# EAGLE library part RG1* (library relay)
HIGH FREQUENCY RELAYS WITH 1C AND 2C CONTACTS NAiS Source: http://www.mew-europe.com/.. en_ds_61302_0000.pdf
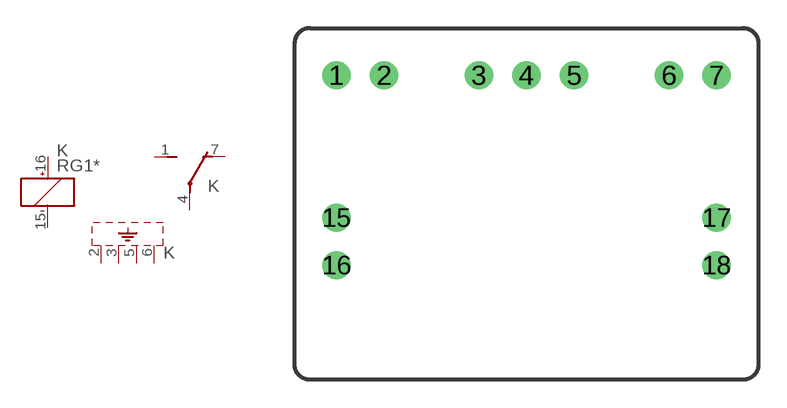
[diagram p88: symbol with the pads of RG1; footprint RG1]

Designator prefix K; gates G$1=K+- G$2=U G$3=SHIELD-4

## RG1-3V (OC_FARNELL: unknown; OC_NEWARK: unknown), RG1-5V (OC_FARNELL: unknown; OC_NEWARK: unknown), RG1-6V (OC_FARNELL: unknown; OC_NEWARK: unknown), RG1-9V (OC_FARNELL: unknown; OC_NEWARK: unknown), RG1-12V (OC_FARNELL: unknown; OC_NEWARK: unknown), RG1-24V (OC_FARNELL: unknown; OC_NEWARK: unknown), RG1-48V (OC_FARNELL: unknown; OC_NEWARK: unknown), RG1T-3V (OC_FARNELL: unknown; OC_NEWARK: unknown), RG1T-5V (OC_FARNELL: unknown; OC_NEWARK: unknown), RG1T-6V (OC_FARNELL: unknown; OC_NEWARK: unknown), RG1T-9V (OC_FARNELL: unknown; OC_NEWARK: unknown), RG1T-12V (OC_FARNELL: unknown; OC_NEWARK: unknown), RG1T-24V (OC_FARNELL: unknown; OC_NEWARK: unknown), RG1T-48V (OC_FARNELL: unknown; OC_NEWARK: unknown)  [RG1]
1  G$2:S  pas
2  G$3:SH  pas
3  G$3:SH  pas
4  G$2:P  pas
5  G$3:SH  pas
6  G$3:SH  pas
7  G$2:O  pas
15  G$1:-  pas
16  G$1:+  pas

## RG1-L (OC_FARNELL: unknown; OC_NEWARK: unknown), RG1-3V-L (OC_FARNELL: unknown; OC_NEWARK: unknown), RG1-5V-L (OC_FARNELL: unknown; OC_NEWARK: unknown), RG1-6V-L (OC_FARNELL: unknown; OC_NEWARK: unknown), RG1-9V-L (OC_FARNELL: unknown; OC_NEWARK: unknown), RG1-12V-L (OC_FARNELL: unknown; OC_NEWARK: unknown), RG1-24V-L (OC_FARNELL: unknown; OC_NEWARK: unknown), RG1-48V-L (OC_FARNELL: unknown; OC_NEWARK: unknown)  [RG1]
1  G$2:S  pas
2  G$3:SH  pas
3  G$3:SH  pas
4  G$2:P  pas
5  G$3:SH  pas
6  G$3:SH  pas
7  G$2:O  pas
15  G$1:+  pas
16  G$1:-  pas

## RG1-3VT-L (OC_FARNELL: unknown; OC_NEWARK: unknown), RG1-5VT-L (OC_FARNELL: unknown; OC_NEWARK: unknown), RG1-6VT-L (OC_FARNELL: unknown; OC_NEWARK: unknown), RG1-9VT-L (OC_FARNELL: unknown; OC_NEWARK: unknown), RG1-12VT-L (OC_FARNELL: unknown; OC_NEWARK: unknown), RG1-24VT-L (OC_FARNELL: unknown; OC_NEWARK: unknown), RG1-48VT-L (OC_FARNELL: unknown; OC_NEWARK: unknown)  [RG1]
Pads as for RG1

## Footprint RG1 (pad centres in mm)
HIGH FREQUENCY RELAYS WITH 1C AND 2C CONTACTS NAiS Source: http://www.mew-europe.com/.. en_ds_61302_0000.pdf
drill 1 round: 1 -10.16,7.62; 2 -7.62,7.62; 3 -2.54,7.62; 4 0,7.62; 5 2.54,7.62; 6 7.62,7.62; 7 10.16,7.62; 15 -10.16,0; 16 -10.16,-2.54; 17 10.16,0; 18 10.16,-2.54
